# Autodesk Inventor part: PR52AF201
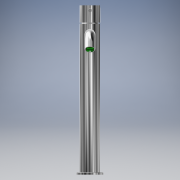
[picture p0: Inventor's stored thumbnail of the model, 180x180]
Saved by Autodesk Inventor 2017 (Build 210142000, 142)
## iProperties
Created: 2021-04
Part Number: PR52AF201
Material: Generico
Document SubType Name: Modeling
Designer: PIZZERA
Density: 1 g/cm^3
Appearance: Default
Author: PIZZERA
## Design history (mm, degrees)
feature "Base4"
node "Solido1"
node "Solido5"
